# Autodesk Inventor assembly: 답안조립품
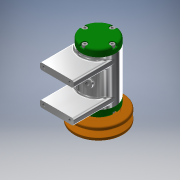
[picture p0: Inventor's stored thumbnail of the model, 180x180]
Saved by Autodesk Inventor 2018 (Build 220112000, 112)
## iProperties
Created: 2020-07
Part Number: 답안조립품
Material: 일반
Document SubType Name: Assembly
Designer: home
Author: home
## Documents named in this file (12)
- C:\Users\home\Desktop\700706V1028\답안조립품.iam
- C:\Users\home\Desktop\700706V1028\본체.ipt
- C:\Users\home\Desktop\700706V1028\베어링 6002.ipt
- C:\Users\home\Desktop\700706V1028\뒤커버.ipt
- C:\Users\home\Desktop\700706V1028\앞커버.ipt
- C:\Users\home\Desktop\700706V1028\축.ipt
- C:\Users\home\Desktop\700706V1028\볼트 M4x12.ipt
- C:\Users\home\Desktop\700706V1028\키 3x3x12.ipt
- C:\Users\home\Desktop\700706V1028\V벨트풀리.ipt
- C:\Users\home\Desktop\700706V1028\와셔 8x17.ipt
- C:\Users\home\Desktop\700706V1028\스프링와셔 8.ipt
- C:\Users\home\Desktop\700706V1028\와셔 6x11.5.ipt
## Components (1 placed, 1 different names)
1. V벨트풀리:1
